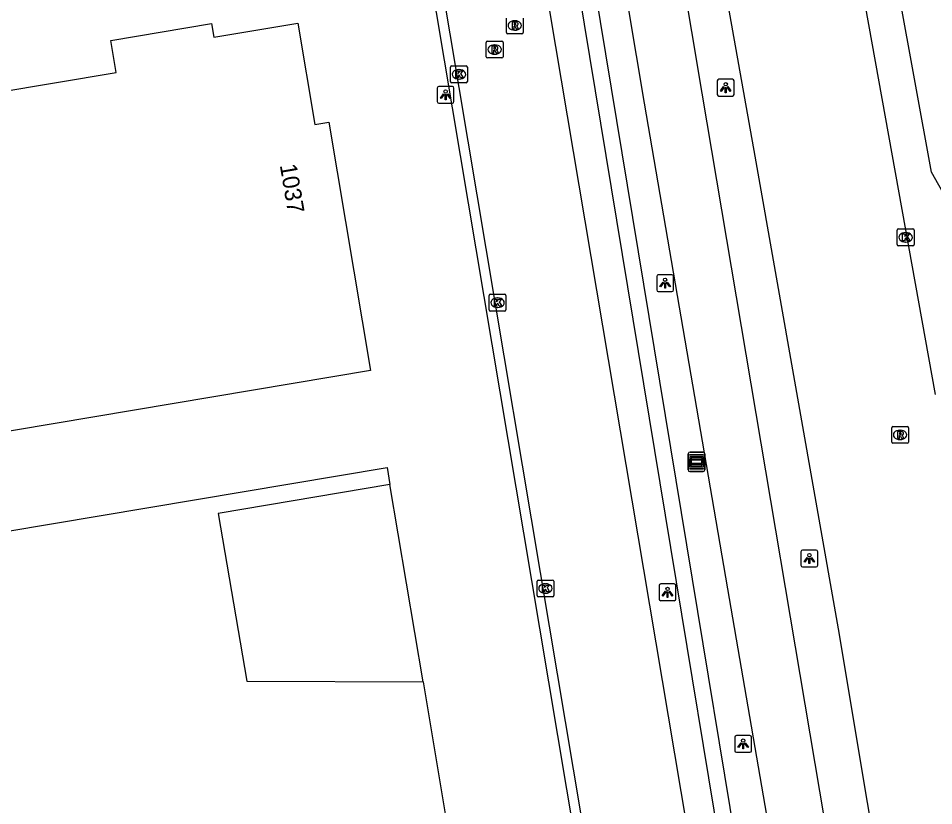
# Model space of a CAD drawing. Extents: x 154324 to 155743, y 382939 to 384183.
# Drawn here: x 155014.9 to 155069.4, y 383519.9 to 383566.8 of the extents above; entities that cross this region are included whole.
import ezdxf

# ---------------------------------------------------------------- set-up
doc = ezdxf.new("R2010")
doc.units = 0
for name, color, linetype in [('IMGEO_Fietspad_gesloten', 7, 'Continuous'), ('IMGEO_Greppel_droge_sloot', 7, 'Continuous'), ('IMGEO_Kolk', 7, 'Continuous'), ('IMGEO_Lichtpunt', 7, 'Continuous'), ('IMGEO_Loofbos', 7, 'Continuous'), ('IMGEO_Pand', 7, 'Continuous'), ('IMGEO_Pand_nummerreeks', 7, 'Continuous'), ('IMGEO_Pand_overbouw', 7, 'Continuous'), ('IMGEO_Rijbaan_lokaal_gesloten', 7, 'Continuous'), ('IMGEO_Rijbaan_lokaal_open', 7, 'Continuous'), ('IMGEO_Rijbaan_regionaal_gesloten', 7, 'Continuous'), ('IMGEO_Rioolput', 7, 'Continuous'), ('IMGEO_Verklikker', 7, 'Continuous')]:
    doc.layers.add(name, color=color, linetype=linetype)

msp = doc.modelspace()

# ---------------------------------------------------------------- linework, layer by layer
at = {"layer": 'IMGEO_Fietspad_gesloten'}
for points in [[(155069.375, 383489.212), (155067.803, 383490.288), (155064.93, 383506.848), (155055.586, 383562.322), (155035.787, 383680.446), (155030.556, 383711.937), (155024.582, 383747.491), (155023.65, 383752.887)], [(155020.155, 383752.117), (155027.003, 383711.594), (155027.513, 383708.543), (155029.197, 383698.769), (155030.596, 383690.066), (155052.123, 383561.719), (155057.1, 383532.805), (155064.796, 383488.095)]]:
    msp.add_lwpolyline(points, dxfattribs=at)
at = {"layer": 'IMGEO_Greppel_droge_sloot'}
for points in [[(155040.514, 383615.174), (155060.78, 383492.297)], [(155061.766, 383492.46), (155041.5, 383615.337)]]:
    msp.add_lwpolyline(points, dxfattribs=at)
at = {"layer": 'IMGEO_Kolk'}
for p, q in [((155040.602, 383563.01), (155040.602, 383563.862)), ((155040.677, 383563.936), (155041.529, 383563.936)), ((155041.603, 383563.862), (155041.603, 383563.01)), ((155041.09, 383563.716), (155041.115, 383563.716)), ((155041.529, 383562.936), (155040.677, 383562.936)), ((155041.113, 383563.156), (155041.088, 383563.156)), ((155067.205, 383553.303), (155067.205, 383554.155)), ((155067.28, 383554.229), (155068.132, 383554.229)), ((155067.693, 383554.009), (155067.718, 383554.009)), ((155068.206, 383554.155), (155068.206, 383553.303)), ((155068.132, 383553.229), (155067.28, 383553.229)), ((155067.716, 383553.449), (155067.691, 383553.449)), ((155042.901, 383549.413), (155042.901, 383550.265)), ((155042.976, 383550.339), (155043.828, 383550.339)), ((155043.902, 383550.265), (155043.902, 383549.413)), ((155043.389, 383550.119), (155043.414, 383550.119)), ((155043.828, 383549.339), (155042.976, 383549.339)), ((155043.412, 383549.559), (155043.387, 383549.559)), ((155045.829, 383533.32), (155046.681, 383533.32)), ((155045.754, 383532.394), (155045.754, 383533.246)), ((155046.242, 383533.1), (155046.267, 383533.1)), ((155046.755, 383533.246), (155046.755, 383532.394)), ((155046.681, 383532.32), (155045.829, 383532.32)), ((155046.265, 383532.54), (155046.24, 383532.54))]:
    msp.add_line(p, q, dxfattribs=at)
for points in [[(155040.602, 383563.01), (155040.602, 383563.862)], [(155040.677, 383563.936), (155041.529, 383563.936)], [(155041.603, 383563.862), (155041.603, 383563.01)], [(155040.923, 383563.636), (155041.046, 383563.636), (155041.046, 383563.485), (155041.176, 383563.636), (155041.34, 383563.636), (155041.194, 383563.485), (155041.347, 383563.236), (155041.195, 383563.236), (155041.11, 383563.4), (155041.046, 383563.333), (155041.046, 383563.236), (155040.923, 383563.236), (155040.923, 383563.636)], [(155041.529, 383562.936), (155040.677, 383562.936)], [(155067.205, 383553.303), (155067.205, 383554.155)], [(155067.28, 383554.229), (155068.132, 383554.229)], [(155068.206, 383554.155), (155068.206, 383553.303)], [(155067.526, 383553.929), (155067.649, 383553.929), (155067.649, 383553.778), (155067.779, 383553.929), (155067.943, 383553.929), (155067.797, 383553.778), (155067.95, 383553.529), (155067.798, 383553.529), (155067.713, 383553.693), (155067.649, 383553.626), (155067.649, 383553.529), (155067.526, 383553.529), (155067.526, 383553.929)], [(155068.132, 383553.229), (155067.28, 383553.229)], [(155042.901, 383549.413), (155042.901, 383550.265)], [(155042.976, 383550.339), (155043.828, 383550.339)], [(155043.902, 383550.265), (155043.902, 383549.413)], [(155043.222, 383550.039), (155043.345, 383550.039), (155043.345, 383549.888), (155043.475, 383550.039), (155043.639, 383550.039), (155043.493, 383549.888), (155043.646, 383549.639), (155043.494, 383549.639), (155043.409, 383549.803), (155043.345, 383549.736), (155043.345, 383549.639), (155043.222, 383549.639), (155043.222, 383550.039)], [(155043.828, 383549.339), (155042.976, 383549.339)], [(155045.829, 383533.32), (155046.681, 383533.32)], [(155045.754, 383532.394), (155045.754, 383533.246)], [(155046.075, 383533.02), (155046.198, 383533.02), (155046.198, 383532.869), (155046.328, 383533.02), (155046.492, 383533.02), (155046.346, 383532.869), (155046.499, 383532.62), (155046.347, 383532.62), (155046.262, 383532.784), (155046.198, 383532.717), (155046.198, 383532.62), (155046.075, 383532.62), (155046.075, 383533.02)], [(155046.755, 383533.246), (155046.755, 383532.394)], [(155046.681, 383532.32), (155045.829, 383532.32)]]:
    msp.add_lwpolyline(points, dxfattribs=at)
for centre, start, end in [((155040.679, 383563.86), 91.552, 178.448), ((155040.679, 383563.86), 91.552, 178.448), ((155041.527, 383563.86), 1.552, 88.448), ((155041.527, 383563.86), 1.552, 88.448), ((155040.679, 383563.012), 181.552, 268.448), ((155040.679, 383563.012), 181.552, 268.448), ((155041.527, 383563.012), 271.552, 358.448), ((155041.527, 383563.012), 271.552, 358.448), ((155067.282, 383554.153), 91.552, 178.448), ((155067.282, 383554.153), 91.552, 178.448), ((155068.13, 383554.153), 1.552, 88.448), ((155068.13, 383554.153), 1.552, 88.448), ((155067.282, 383553.305), 181.552, 268.448), ((155067.282, 383553.305), 181.552, 268.448), ((155068.13, 383553.305), 271.552, 358.448), ((155068.13, 383553.305), 271.552, 358.448), ((155042.978, 383550.263), 91.552, 178.448), ((155042.978, 383550.263), 91.552, 178.448), ((155043.826, 383550.263), 1.552, 88.448), ((155043.826, 383550.263), 1.552, 88.448), ((155042.978, 383549.415), 181.552, 268.448), ((155042.978, 383549.415), 181.552, 268.448), ((155043.826, 383549.415), 271.552, 358.448), ((155043.826, 383549.415), 271.552, 358.448), ((155045.831, 383533.244), 91.552, 178.448), ((155045.831, 383533.244), 91.552, 178.448), ((155046.679, 383533.244), 1.552, 88.448), ((155046.679, 383533.244), 1.552, 88.448), ((155045.831, 383532.396), 181.552, 268.448), ((155045.831, 383532.396), 181.552, 268.448), ((155046.679, 383532.396), 271.552, 358.448), ((155046.679, 383532.396), 271.552, 358.448)]:
    msp.add_arc(centre, 0.0765, start, end, dxfattribs=at)
for centre, major_axis, ratio, start_param, end_param in [((155041.089, 383563.436), (-0.387, 0.002), 0.722429, 4.712389, 7.853982), ((155041.114, 383563.436), (-0.39, 0.002), 0.717154, 1.570796, 4.712389), ((155067.692, 383553.729), (-0.387, 0.002), 0.722429, 4.712389, 7.853982), ((155067.717, 383553.729), (-0.39, 0.002), 0.717154, 1.570796, 4.712389), ((155043.388, 383549.839), (-0.387, 0.002), 0.722429, 4.712389, 7.853982), ((155043.413, 383549.839), (-0.39, 0.002), 0.717154, 1.570796, 4.712389), ((155046.241, 383532.82), (-0.387, 0.002), 0.722429, 4.712389, 7.853982), ((155046.266, 383532.82), (-0.39, 0.002), 0.717154, 1.570796, 4.712389)]:
    msp.add_ellipse(centre, major_axis=major_axis, ratio=ratio, start_param=start_param, end_param=end_param, dxfattribs=at)
at = {"layer": 'IMGEO_Lichtpunt'}
for p, q in [((155056.488, 383563.045), (155056.488, 383562.238)), ((155056.488, 383563.045), (155056.488, 383562.238)), ((155057.39, 383563.14), (155056.582, 383563.14)), ((155057.39, 383563.14), (155056.582, 383563.14)), ((155057.484, 383562.238), (155057.484, 383563.045)), ((155057.484, 383562.238), (155057.484, 383563.045)), ((155039.81, 383562.617), (155039.81, 383561.81)), ((155039.81, 383562.617), (155039.81, 383561.81)), ((155040.712, 383562.712), (155039.904, 383562.712)), ((155040.712, 383562.712), (155039.904, 383562.712)), ((155040.806, 383561.81), (155040.806, 383562.617)), ((155040.806, 383561.81), (155040.806, 383562.617)), ((155039.904, 383561.716), (155040.712, 383561.716)), ((155039.904, 383561.716), (155040.712, 383561.716)), ((155056.582, 383562.144), (155057.39, 383562.144)), ((155056.582, 383562.144), (155057.39, 383562.144)), ((155052.882, 383551.404), (155052.882, 383550.597)), ((155052.882, 383551.404), (155052.882, 383550.597)), ((155053.784, 383551.499), (155052.976, 383551.499)), ((155053.784, 383551.499), (155052.976, 383551.499)), ((155053.878, 383550.597), (155053.878, 383551.404)), ((155053.878, 383550.597), (155053.878, 383551.404)), ((155052.976, 383550.503), (155053.784, 383550.503)), ((155052.976, 383550.503), (155053.784, 383550.503)), ((155061.471, 383535.006), (155061.471, 383534.199)), ((155061.471, 383535.006), (155061.471, 383534.199)), ((155062.373, 383535.101), (155061.565, 383535.101)), ((155062.373, 383535.101), (155061.565, 383535.101)), ((155062.467, 383534.199), (155062.467, 383535.006)), ((155062.467, 383534.199), (155062.467, 383535.006)), ((155061.565, 383534.105), (155062.373, 383534.105)), ((155061.565, 383534.105), (155062.373, 383534.105)), ((155053.026, 383532.996), (155053.026, 383532.189)), ((155053.026, 383532.996), (155053.026, 383532.189)), ((155053.928, 383533.091), (155053.12, 383533.091)), ((155053.928, 383533.091), (155053.12, 383533.091)), ((155054.022, 383532.189), (155054.022, 383532.996)), ((155054.022, 383532.189), (155054.022, 383532.996)), ((155053.12, 383532.095), (155053.928, 383532.095)), ((155053.12, 383532.095), (155053.928, 383532.095)), ((155058.432, 383524.063), (155057.624, 383524.063)), ((155058.432, 383524.063), (155057.624, 383524.063)), ((155057.53, 383523.968), (155057.53, 383523.161)), ((155057.53, 383523.968), (155057.53, 383523.161)), ((155058.526, 383523.161), (155058.526, 383523.968)), ((155058.526, 383523.161), (155058.526, 383523.968)), ((155057.624, 383523.067), (155058.432, 383523.067)), ((155057.624, 383523.067), (155058.432, 383523.067))]:
    msp.add_line(p, q, dxfattribs=at)
for points in [[(155040.184, 383562.281), (155040.223, 383562.253), (155040.035, 383561.991), (155039.997, 383562.018), (155040.184, 383562.281)], [(155040.286, 383562.233), (155040.333, 383562.233), (155040.333, 383561.911), (155040.286, 383561.911), (155040.286, 383562.233)], [(155040.396, 383562.253), (155040.434, 383562.28), (155040.621, 383562.018), (155040.582, 383561.99), (155040.396, 383562.253)], [(155056.862, 383562.709), (155056.901, 383562.681), (155056.713, 383562.419), (155056.675, 383562.446), (155056.862, 383562.709)], [(155056.964, 383562.661), (155057.011, 383562.661), (155057.011, 383562.339), (155056.964, 383562.339), (155056.964, 383562.661)], [(155057.074, 383562.681), (155057.112, 383562.708), (155057.299, 383562.446), (155057.26, 383562.418), (155057.074, 383562.681)], [(155053.256, 383551.068), (155053.295, 383551.04), (155053.107, 383550.778), (155053.069, 383550.805), (155053.256, 383551.068)], [(155053.358, 383551.02), (155053.405, 383551.02), (155053.405, 383550.698), (155053.358, 383550.698), (155053.358, 383551.02)], [(155053.468, 383551.04), (155053.506, 383551.067), (155053.693, 383550.805), (155053.654, 383550.777), (155053.468, 383551.04)], [(155061.845, 383534.67), (155061.884, 383534.642), (155061.696, 383534.38), (155061.658, 383534.407), (155061.845, 383534.67)], [(155061.947, 383534.622), (155061.994, 383534.622), (155061.994, 383534.3), (155061.947, 383534.3), (155061.947, 383534.622)], [(155062.057, 383534.642), (155062.095, 383534.669), (155062.282, 383534.407), (155062.243, 383534.379), (155062.057, 383534.642)], [(155053.4, 383532.66), (155053.439, 383532.632), (155053.251, 383532.37), (155053.213, 383532.397), (155053.4, 383532.66)], [(155053.502, 383532.612), (155053.549, 383532.612), (155053.549, 383532.29), (155053.502, 383532.29), (155053.502, 383532.612)], [(155053.612, 383532.632), (155053.65, 383532.659), (155053.837, 383532.397), (155053.798, 383532.369), (155053.612, 383532.632)], [(155057.904, 383523.632), (155057.943, 383523.604), (155057.755, 383523.342), (155057.717, 383523.369), (155057.904, 383523.632)], [(155058.006, 383523.584), (155058.053, 383523.584), (155058.053, 383523.262), (155058.006, 383523.262), (155058.006, 383523.584)], [(155058.116, 383523.604), (155058.154, 383523.631), (155058.341, 383523.369), (155058.302, 383523.341), (155058.116, 383523.604)]]:
    msp.add_lwpolyline(points, dxfattribs=at)
for centre in [(155056.987, 383562.843), (155040.309, 383562.415), (155053.381, 383551.202), (155061.97, 383534.804), (155053.525, 383532.794), (155058.029, 383523.766)]:
    msp.add_circle(centre, 0.0994, dxfattribs=at)
for centre, start, end in [((155056.582, 383563.045), 90, 180), ((155056.582, 383563.045), 90, 180), ((155057.39, 383563.045), 0, 90), ((155057.39, 383563.045), 0, 90), ((155039.904, 383562.617), 90, 180), ((155039.904, 383562.617), 90, 180), ((155040.712, 383562.617), 0, 90), ((155040.712, 383562.617), 0, 90), ((155056.582, 383562.238), 180, 270), ((155056.582, 383562.238), 180, 270), ((155057.39, 383562.238), 270, 0), ((155057.39, 383562.238), 270, 360), ((155039.904, 383561.81), 180, 270), ((155039.904, 383561.81), 180, 270), ((155040.712, 383561.81), 270, 0), ((155040.712, 383561.81), 270, 360), ((155052.976, 383551.404), 90, 180), ((155052.976, 383551.404), 90, 180), ((155053.784, 383551.404), 0, 90), ((155053.784, 383551.404), 0, 90), ((155052.976, 383550.597), 180, 270), ((155052.976, 383550.597), 180, 270), ((155053.784, 383550.597), 270, 0), ((155053.784, 383550.597), 270, 360), ((155061.565, 383535.006), 90, 180), ((155061.565, 383535.006), 90, 180), ((155062.373, 383535.006), 0, 90), ((155062.373, 383535.006), 0, 90), ((155061.565, 383534.199), 180, 270), ((155061.565, 383534.199), 180, 270), ((155062.373, 383534.199), 270, 0), ((155062.373, 383534.199), 270, 360), ((155053.12, 383532.996), 90, 180), ((155053.12, 383532.996), 90, 180), ((155053.928, 383532.996), 0, 90), ((155053.928, 383532.996), 0, 90), ((155053.12, 383532.189), 180, 270), ((155053.12, 383532.189), 180, 270), ((155053.928, 383532.189), 270, 0), ((155053.928, 383532.189), 270, 360), ((155057.624, 383523.968), 90, 180), ((155057.624, 383523.968), 90, 180), ((155058.432, 383523.968), 0, 90), ((155058.432, 383523.968), 0, 90), ((155057.624, 383523.161), 180, 270), ((155057.624, 383523.161), 180, 270), ((155058.432, 383523.161), 270, 0), ((155058.432, 383523.161), 270, 360)]:
    msp.add_arc(centre, 0.0946, start, end, dxfattribs=at)
at = {"layer": 'IMGEO_Loofbos'}
msp.add_lwpolyline([(155150.12, 383546.849), (155147.672, 383535.525), (155141.293, 383537.615), (155133.684, 383529.375), (155124.807, 383520.48), (155115.997, 383521.813), (155107.115, 383520.76), (155104.634, 383525.749), (155106.245, 383533.735), (155095.073, 383538.97), (155091.938, 383544.397), (155085.842, 383544.943), (155077.749, 383551.031), (155073.706, 383549.691), (155069.247, 383557.613), (155064.414, 383584.109), (155059.736, 383616.398), (155060.565, 383620.426)], dxfattribs=at)
at = {"layer": 'IMGEO_Pand'}
for points in [[(154969.786, 383534.713), (154965.666, 383559.473), (154973.186, 383560.734), (154974.005, 383555.725), (155020.689, 383563.542), (155020.365, 383565.454), (155026.369, 383566.472), (155026.509, 383565.644), (155031.506, 383566.491), (155032.52, 383560.445), (155033.349, 383560.584), (155035.827, 383545.808), (154969.786, 383534.713)], [(154995.441, 383472.207), (154985.474, 383531.415), (155036.823, 383540.015), (155036.983, 383539.019), (155026.768, 383537.289), (155028.46, 383527.301), (155038.974, 383527.261), (155040.294, 383519.291), (155030.102, 383517.603), (155031.749, 383507.659), (155042.274, 383507.548), (155043.622, 383499.583), (155033.407, 383497.855), (155035.104, 383487.827), (155045.588, 383487.816), (155046.763, 383480.845), (154995.441, 383472.207)]]:
    msp.add_lwpolyline(points, dxfattribs=at)
at = {"layer": 'IMGEO_Pand_overbouw'}
msp.add_lwpolyline([(155038.974, 383527.261), (155036.983, 383539.019), (155026.768, 383537.289), (155028.46, 383527.301)], close=True, dxfattribs=at)
at = {"layer": 'IMGEO_Rijbaan_lokaal_gesloten'}
for points in [[(155059.928, 383487.45), (155052.477, 383531.831), (155025.49, 383692.18), (155022.669, 383708.88), (155021.296, 383718.742)], [(155059.439, 383453.463), (155046.503, 383530.572), (155016.871, 383707.197)]]:
    msp.add_lwpolyline(points, dxfattribs=at)
at = {"layer": 'IMGEO_Rijbaan_lokaal_open'}
msp.add_lwpolyline([(155065.709, 383396.485), (155065.341, 383401.33), (155064.659, 383408.986), (155063.139, 383423.564), (155063.03, 383424.403), (155061.613, 383435.27), (155060.487, 383443.041), (155058.846, 383453.397), (155045.918, 383530.449), (155024.164, 383660.104), (155016.277, 383707.107)], dxfattribs=at)
at = {"layer": 'IMGEO_Rijbaan_regionaal_gesloten'}
for points in [[(155023.592, 383759.163), (155025.319, 383747.582), (155031.523, 383712.699), (155040.998, 383657.511), (155047.66, 383620.638), (155058.726, 383558.566), (155063.68, 383530.41), (155070.593, 383489.047)], [(155030.993, 383757.82), (155045.927, 383675.069), (155050.278, 383650.736), (155055.096, 383623.794), (155056.54, 383616.113), (155069.465, 383544.367)]]:
    msp.add_lwpolyline(points, dxfattribs=at)
at = {"layer": 'IMGEO_Rioolput'}
for p, q in [((155043.926, 383565.921), (155043.926, 383566.773)), ((155044.414, 383566.627), (155044.439, 383566.627)), ((155044.927, 383566.773), (155044.927, 383565.921)), ((155044.437, 383566.067), (155044.412, 383566.067)), ((155044.853, 383565.847), (155044.001, 383565.847)), ((155042.727, 383564.486), (155042.727, 383565.338)), ((155042.802, 383565.412), (155043.654, 383565.412)), ((155043.215, 383565.192), (155043.24, 383565.192)), ((155043.728, 383565.338), (155043.728, 383564.486)), ((155043.654, 383564.412), (155042.802, 383564.412)), ((155043.238, 383564.632), (155043.213, 383564.632)), ((155066.875, 383541.54), (155066.875, 383542.392)), ((155066.95, 383542.466), (155067.802, 383542.466)), ((155067.363, 383542.246), (155067.388, 383542.246)), ((155067.876, 383542.392), (155067.876, 383541.54)), ((155067.802, 383541.466), (155066.95, 383541.466)), ((155067.386, 383541.686), (155067.361, 383541.686))]:
    msp.add_line(p, q, dxfattribs=at)
for points in [[(155043.926, 383565.921), (155043.926, 383566.773)], [(155044.515, 383566.545), (155044.263, 383566.547), (155044.263, 383566.147)], [(155044.927, 383566.773), (155044.927, 383565.921)], [(155044.263, 383566.147), (155044.387, 383566.147), (155044.387, 383566.309), (155044.398, 383566.309)], [(155044.441, 383566.466), (155044.387, 383566.466), (155044.387, 383566.385)], [(155044.387, 383566.385), (155044.439, 383566.385)], [(155044.445, 383566.28), (155044.516, 383566.147), (155044.656, 383566.147), (155044.591, 383566.273)], [(155044.853, 383565.847), (155044.001, 383565.847)], [(155042.727, 383564.486), (155042.727, 383565.338)], [(155042.802, 383565.412), (155043.654, 383565.412)], [(155043.316, 383565.11), (155043.064, 383565.112), (155043.064, 383564.712)], [(155043.242, 383565.031), (155043.188, 383565.031), (155043.188, 383564.95)], [(155043.188, 383564.95), (155043.24, 383564.95)], [(155043.728, 383565.338), (155043.728, 383564.486)], [(155043.654, 383564.412), (155042.802, 383564.412)], [(155043.064, 383564.712), (155043.188, 383564.712), (155043.188, 383564.874), (155043.199, 383564.874)], [(155043.246, 383564.845), (155043.317, 383564.712), (155043.457, 383564.712), (155043.392, 383564.838)], [(155066.875, 383541.54), (155066.875, 383542.392)], [(155066.95, 383542.466), (155067.802, 383542.466)], [(155067.464, 383542.164), (155067.212, 383542.166), (155067.212, 383541.766)], [(155067.39, 383542.085), (155067.336, 383542.085), (155067.336, 383542.004)], [(155067.876, 383542.392), (155067.876, 383541.54)], [(155067.802, 383541.466), (155066.95, 383541.466)], [(155067.212, 383541.766), (155067.336, 383541.766), (155067.336, 383541.928), (155067.347, 383541.928)], [(155067.336, 383542.004), (155067.388, 383542.004)], [(155067.394, 383541.899), (155067.465, 383541.766), (155067.605, 383541.766), (155067.54, 383541.892)]]:
    msp.add_lwpolyline(points, dxfattribs=at)
for centre, radius, start, end in [((155044.514, 383566.435), 0.109, 350.3612, 89.416), ((155044.397, 383566.256), 0.0533, 26.0293, 88.6989), ((155044.423, 383566.574), 0.19, 274.7715, 282.9687), ((155044.447, 383566.37), 0.0964, 77.0061, 93.1865), ((155044.461, 383566.427), 0.0378, 276.6634, 79.6772), ((155044.512, 383566.435), 0.112, 277.5842, 350.9817), ((155044.496, 383566.22), 0.108, 29.5134, 73.7905), ((155044.003, 383565.923), 0.0765, 181.552, 268.448), ((155044.003, 383565.923), 0.0765, 181.552, 268.448), ((155044.851, 383565.923), 0.0765, 271.552, 358.448), ((155044.851, 383565.923), 0.0765, 271.552, 358.448), ((155042.804, 383565.336), 0.0765, 91.552, 178.448), ((155042.804, 383565.336), 0.0765, 91.552, 178.448), ((155043.224, 383565.139), 0.19, 274.7715, 282.9687), ((155043.248, 383564.935), 0.0964, 77.0061, 93.1865), ((155043.262, 383564.992), 0.0378, 276.6634, 79.6772), ((155043.315, 383565), 0.109, 350.3612, 89.416), ((155043.313, 383565), 0.112, 277.5842, 350.9817), ((155043.652, 383565.336), 0.0765, 1.552, 88.448), ((155043.652, 383565.336), 0.0765, 1.552, 88.448), ((155042.804, 383564.488), 0.0765, 181.552, 268.448), ((155042.804, 383564.488), 0.0765, 181.552, 268.448), ((155043.198, 383564.821), 0.0533, 26.0293, 88.6989), ((155043.297, 383564.785), 0.108, 29.5134, 73.7905), ((155043.652, 383564.488), 0.0765, 271.552, 358.448), ((155043.652, 383564.488), 0.0765, 271.552, 358.448), ((155066.952, 383542.39), 0.0765, 91.552, 178.448), ((155066.952, 383542.39), 0.0765, 91.552, 178.448), ((155067.372, 383542.193), 0.19, 274.7715, 282.9687), ((155067.396, 383541.989), 0.0964, 77.0061, 93.1865), ((155067.41, 383542.046), 0.0378, 276.6634, 79.6772), ((155067.463, 383542.054), 0.109, 350.3612, 89.416), ((155067.461, 383542.054), 0.112, 277.5842, 350.9817), ((155067.8, 383542.39), 0.0765, 1.552, 88.448), ((155067.8, 383542.39), 0.0765, 1.552, 88.448), ((155066.952, 383541.542), 0.0765, 181.552, 268.448), ((155066.952, 383541.542), 0.0765, 181.552, 268.448), ((155067.346, 383541.875), 0.0533, 26.0293, 88.6989), ((155067.445, 383541.839), 0.108, 29.5134, 73.7905), ((155067.8, 383541.542), 0.0765, 271.552, 358.448), ((155067.8, 383541.542), 0.0765, 271.552, 358.448)]:
    msp.add_arc(centre, radius, start, end, dxfattribs=at)
for centre, major_axis, ratio, start_param, end_param in [((155044.413, 383566.347), (-0.387, 0.002), 0.722429, 4.712389, 7.853982), ((155044.438, 383566.347), (-0.39, 0.002), 0.717154, 1.570796, 4.712389), ((155043.214, 383564.912), (-0.387, 0.002), 0.722429, 4.712389, 7.853982), ((155043.239, 383564.912), (-0.39, 0.002), 0.717154, 1.570796, 4.712389), ((155067.362, 383541.966), (-0.387, 0.002), 0.722429, 4.712389, 7.853982), ((155067.387, 383541.966), (-0.39, 0.002), 0.717154, 1.570796, 4.712389)]:
    msp.add_ellipse(centre, major_axis=major_axis, ratio=ratio, start_param=start_param, end_param=end_param, dxfattribs=at)
at = {"layer": 'IMGEO_Verklikker'}
for p, q in [((155054.862, 383540.941), (155055.652, 383540.941)), ((155055.652, 383540.941), (155054.862, 383540.941)), ((155054.748, 383539.886), (155054.748, 383540.686)), ((155054.748, 383540.686), (155054.748, 383539.886)), ((155054.762, 383540.041), (155054.762, 383540.841)), ((155054.762, 383540.841), (155054.762, 383540.041)), ((155054.848, 383540.786), (155055.638, 383540.786)), ((155055.638, 383540.786), (155054.848, 383540.786)), ((155055.738, 383540.686), (155055.738, 383539.886)), ((155055.738, 383539.886), (155055.738, 383540.686)), ((155055.752, 383540.841), (155055.752, 383540.041)), ((155055.752, 383540.041), (155055.752, 383540.841)), ((155055.652, 383539.941), (155054.862, 383539.941)), ((155054.862, 383539.941), (155055.652, 383539.941)), ((155055.638, 383539.786), (155054.848, 383539.786)), ((155054.848, 383539.786), (155055.638, 383539.786))]:
    msp.add_line(p, q, dxfattribs=at)
for points in [[(155054.849, 383540.518), (155055.637, 383540.518), (155055.637, 383540.054), (155054.849, 383540.054), (155054.849, 383540.518)], [(155054.863, 383540.673), (155055.651, 383540.673), (155055.651, 383540.209), (155054.863, 383540.209), (155054.863, 383540.673)], [(155054.914, 383540.453), (155054.914, 383540.119), (155055.572, 383540.119), (155055.572, 383540.453), (155054.914, 383540.453)], [(155054.928, 383540.608), (155054.928, 383540.274), (155055.586, 383540.274), (155055.586, 383540.608), (155054.928, 383540.608)]]:
    msp.add_lwpolyline(points, dxfattribs=at)
for centre, start, end in [((155054.862, 383540.841), 90, 180), ((155054.862, 383540.841), 90, 180), ((155055.652, 383540.841), 0, 90), ((155055.652, 383540.841), 360, 90), ((155054.848, 383540.686), 90, 180), ((155054.848, 383540.686), 90, 180), ((155055.638, 383540.686), 0, 90), ((155055.638, 383540.686), 360, 90), ((155054.848, 383539.886), 180, 270), ((155054.848, 383539.886), 180, 270), ((155054.862, 383540.041), 180, 270), ((155054.862, 383540.041), 180, 270), ((155055.638, 383539.886), 270, 0), ((155055.638, 383539.886), 270, 0), ((155055.652, 383540.041), 270, 0), ((155055.652, 383540.041), 270, 0)]:
    msp.add_arc(centre, 0.1, start, end, dxfattribs=at)

# ---------------------------------------------------------------- texts
at = {"layer": 'IMGEO_Pand_nummerreeks'}
msp.add_text('1037', height=1, rotation=279.6171, dxfattribs=at).set_placement((155030.43, 383558.026))

doc.saveas('drawing.dxf')
